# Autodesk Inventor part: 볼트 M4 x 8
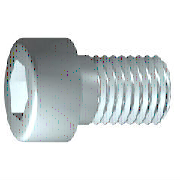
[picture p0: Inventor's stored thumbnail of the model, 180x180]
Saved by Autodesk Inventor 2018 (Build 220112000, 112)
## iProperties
IsCustomPart: 0
Created: 2012-02
Part Number: 볼트 M4 x 8
Material: 스테인리스강
Description: 6각 소켓 머리 캡 나사
Document SubType Name: Modeling
Standard: ISO 4762
Designer: mduedu
Standard Revision: Fourth edition 2004-03-01
Standards Organization: ISO
Language: ko-KR
Size Designation: M4 x 8
Categories: <MemberInstance><Categories><Category DisplayName="조임쇠" InternalName="e4da775c-781d-43d5-af7c-5136215cf5a6" Mnemonic="FSTN"><Category DisplayName="볼트" InternalN
Density: 8.08 g/cm^3
Appearance: 반광택
Mass: 1.89105 g
Surface Area: 2.80587 cm^2
Volume: 0.234041 cm^3
Author: mduedu
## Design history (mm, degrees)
sketch "스케치1"
  geometry: L1 (-1, 0)-(8, 0); L2 (8, 0)-(8, 2); L3 (8, 2)-(1.75, 2); L4 (1.75, 2)-(1.32, 2); L5 (1.32, 2)-(0, 2); L6 (0, 2)-(0, 3.5); L7 (0, 3.5)-(-4, 3.5); L8 (-4, 3.5)-(-4, 1.732); L9 (-4, 1.732)-(-2, 1.732); L10 (-2, 1.732)-(-1, 0); L11 (-6.4, 0)-(10.4, 0) reference; L12 (0, -0.7)-(0, 4.2) reference; L13 (1.75, 2)-(0, 2)
  constraints: 22 end point, 6 parallel, 2 collinear, 2 perpendicular, 1 horizontal, 1 point on line
  dimensions: "d1" = 6.25 distance from line of L3.end L2 (= GEL); "d2" = 0.42952 distance of L4.end L3.end (computed from GAL); "d3" = 4 distance between parallel lines of L8 L6 (= KOH); "d4" = 2 distance of L8.end L9.end (= INTI); "d5" = 60 deg angle of L10 L1; "d6" = 4 diameter of L3 L1 (= GD); "d7" = 4 diameter of L5 L1 (= BDM); "d8" = 3.4641 diameter of L9 L1 (= 1.1547 x SW); "d9" = 7 diameter of L7 L1 (= KOD); "d26" = 8 distance between parallel lines of L12 L2 (= NLG)
revolve "본체" sketch "스케치1" stored, may be unused: angle "d10" = 90 deg
sketch "스케치2"
  geometry: L1 (0, -4.9)-(0, 4.9) reference; L2 (-4.9, 0)-(4.9, 0) reference; L3 (1.732, 0)-(0.866, -1.5); L4 (0.866, -1.5)-(-0.866, -1.5); L5 (-0.866, -1.5)-(-1.732, 0); L6 (-1.732, 0)-(-0.866, 1.5); L7 (-0.866, 1.5)-(0.866, 1.5); L8 (0.866, 1.5)-(1.732, 0); 2 further points
  constraints: 12 end point, 1 coincident, 1 horizontal alignment, 1 point on line, 12 other
extrude "슬롯" join sketch "스케치2" stored distance "d11" = 10; taper "d12" = 0 deg
workplane "Work Plane1"
fillet "Fillet2" dims "d30" = 0.1 (= R)
body "Solid1"
fillet "모깎기1" dims "d17" = 0.4 (= RR)
feature "스레드" dims "d13" = 6.25 (= GEL), "d14" = 0
chamfer "모따기1" distance "d15" = 0.42941 (= -0.5 x SPD + 0.5 x GD); stored, may be unused: second distance "d16" = 0.42941 (= GUL), angle "d27" = 45 deg
other parameters: "GD" = 4 [user parameter; used in 2 equation terms], "NLG" = 8 [user parameter; used in 1 equation term], "GEL" = 6.25 [user parameter; used in 2 equation terms], "KOD" = 7 [user parameter; used in 1 equation term], "KOH" = 4 [user parameter; used in 1 equation term], "INTI" = 2 [user parameter; used in 1 equation term], "GAL" = 0.42941 (= 0.61345 x PTC) [user parameter; used in 1 equation term], "GUL" = 0.42941 (= 0.61345 x PTC) [user parameter; used in 1 equation term], "BDM" = 4 (= NND) [user parameter; used in 1 equation term], "SW" = 3 [user parameter; used in 2 equation terms], "RR" = 0.4 [user parameter; used in 1 equation term], "SPD" = 3.14117 (= NND - 1.2269 x PTC) [user parameter; used in 1 equation term], "d19" = 0, "d28" = 0, "d29" = 0, "R" = 0.1 [user parameter; used in 1 equation term], "TOA" = 30 deg [user parameter], "GD1" = 3.14117 (= THREADDIA - 1.2269 x PTC) [user parameter], "THREADDIA" = 4 [user parameter; used in 1 equation term], "FAWI" = 45 deg [user parameter], "TPU" = 14.28571 (computed from PTC) [user parameter], "PTC" = 0.7 [user parameter; used in 5 equation terms], "NND" = 4 [user parameter; used in 2 equation terms], "E0" = 3.465 (= 1.155 x SW) [user parameter]
